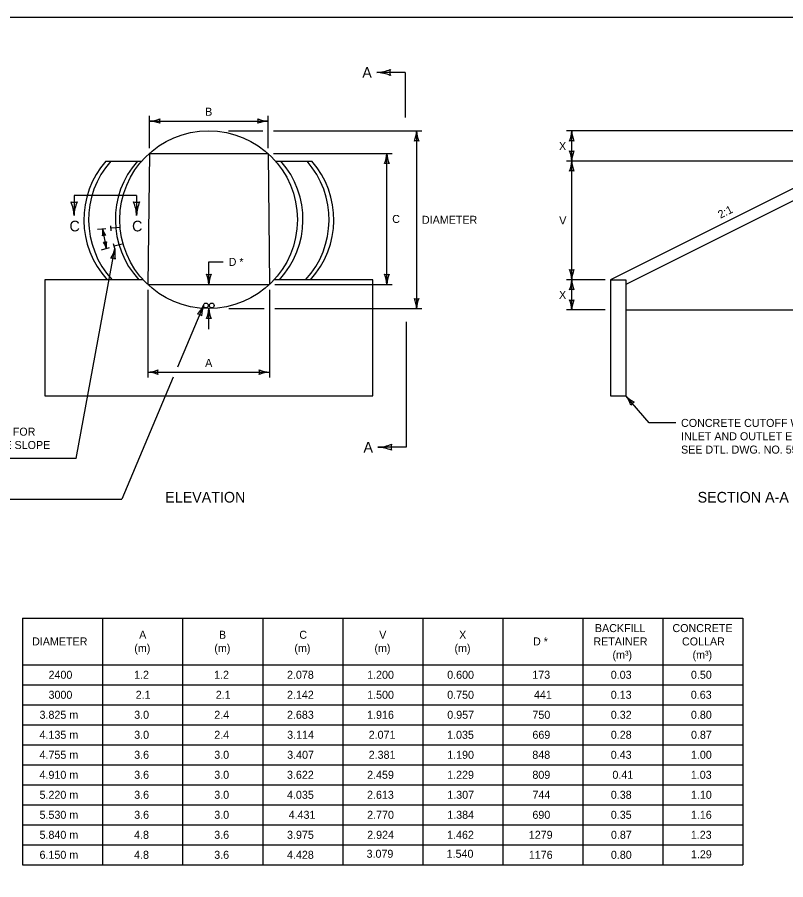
# Model space of a CAD drawing. Extents: x 49991.4 to 50021, y 49987.6 to 50011.4.
# Drawn here: x 50003.93 to 50009.69, y 49992.53 to 49999 of the extents above; entities that cross this region are included whole.
import ezdxf

# ---------------------------------------------------------------- set-up
doc = ezdxf.new("R2010")
doc.units = 0
for name, color, linetype in [('Level 1', 7, 'Continuous'), ('Level 2', 7, 'Continuous'), ('Level 3', 7, 'Continuous'), ('Level 4', 7, 'Continuous'), ('Level 6', 7, 'Continuous')]:
    doc.layers.add(name, color=color, linetype=linetype)

msp = doc.modelspace()

# ---------------------------------------------------------------- linework, layer by layer
at = {"layer": 'Level 1'}
for p, q in [((50004.5961, 49997.9206), (50004.8654, 49997.9206)), ((50005.8667, 49997.9206), (50006.1399, 49997.9206)), ((50010.1574, 49997.9206), (50008.3776, 49997.0307)), ((50010.3438, 49997.9206), (50008.4946, 49996.996)), ((50004.6363, 49997.3988), (50004.6331, 49997.4356)), ((50004.7061, 49997.4235), (50004.6347, 49997.4172)), ((50004.6643, 49997.2641), (50004.6543, 49997.2996)), ((50004.7284, 49997.3012), (50004.6593, 49997.2818)), ((50004.8754, 49997.0307), (50004.1392, 49997.0307)), ((50004.1392, 49997.0307), (50004.1392, 49996.1603)), ((50004.9097, 49996.996), (50005.8221, 49996.996)), ((50006.5966, 49997.0307), (50005.8565, 49997.0307)), ((50006.5966, 49996.1603), (50006.5966, 49997.0307)), ((50008.3776, 49997.0307), (50008.3776, 49996.1603)), ((50008.3776, 49997.0307), (50008.4946, 49997.0307)), ((50008.4946, 49997.0307), (50008.4946, 49996.9917)), ((50008.4946, 49996.9917), (50008.4946, 49996.1603)), ((50008.4946, 49996.8045), (50010.4571, 49996.8045)), ((50008.3776, 49996.3989), (50008.3776, 49996.3989)), ((50004.1392, 49996.1603), (50006.5966, 49996.1603)), ((50008.3776, 49996.1603), (50008.4946, 49996.1603))]:
    msp.add_line(p, q, dxfattribs=at)
msp.add_lwpolyline([(49999.3835, 49998.9992), (50016.7501, 49998.9992), (50016.7501, 49987.7988), (49999.3835, 49987.7988)], close=True, dxfattribs=at)
for centre, radius in [((50005.3659, 49997.4814), 0.6662), ((50005.3461, 49996.8376), 0.0179), ((50005.3897, 49996.8376), 0.0179)]:
    msp.add_circle(centre, radius, dxfattribs=at)
for centre, start, end in [((50005.0969, 49997.4814), 138.75266, 222.57653), ((50005.6391, 49997.4814), 317.42347, 41.24734)]:
    msp.add_arc(centre, 0.6662, start, end, dxfattribs=at)
at = {"layer": 'Level 2'}
for p, q in [((50003.9717, 49994.4938), (50009.3715, 49994.4938)), ((50003.9717, 49994.4938), (50003.9717, 49992.6438)), ((50004.5715, 49994.4938), (50004.5715, 49992.6438)), ((50005.1715, 49994.4938), (50005.1715, 49992.6438)), ((50005.7715, 49994.4938), (50005.7715, 49992.6438)), ((50006.3715, 49994.4938), (50006.3715, 49992.6438)), ((50006.9715, 49994.4938), (50006.9715, 49992.6438)), ((50007.5715, 49994.4938), (50007.5715, 49992.6438)), ((50008.1715, 49994.4938), (50008.1715, 49992.6438)), ((50008.7715, 49994.4938), (50008.7715, 49992.6438)), ((50009.3715, 49994.4938), (50009.3715, 49992.6438)), ((50003.9717, 49994.1438), (50009.3715, 49994.1438)), ((50003.9717, 49993.9938), (50009.3715, 49993.9938)), ((50003.9717, 49993.8438), (50009.3715, 49993.8438)), ((50003.9717, 49993.6938), (50009.3715, 49993.6938)), ((50003.9717, 49993.5438), (50009.3715, 49993.5438)), ((50003.9717, 49993.3938), (50009.3715, 49993.3938)), ((50003.9717, 49993.2438), (50009.3715, 49993.2438)), ((50003.9717, 49993.0938), (50009.3715, 49993.0938)), ((50003.9717, 49992.9438), (50009.3715, 49992.9438)), ((50003.9717, 49992.7938), (50009.3715, 49992.7938)), ((50003.9719, 49992.6438), (50009.3717, 49992.6438))]:
    msp.add_line(p, q, dxfattribs=at)
at = {"layer": 'Level 3'}
for p, q in [((50004.9237, 49998.0177), (50004.9237, 49998.2609)), ((50004.9237, 49998.2209), (50005.812, 49998.2209)), ((50005.812, 49998.0177), (50005.812, 49998.2609)), ((50005.5159, 49998.1464), (50005.772, 49998.1464)), ((50005.852, 49998.1464), (50006.9653, 49998.1464)), ((50006.9253, 49998.1464), (50006.9253, 49996.8141)), ((50010.1174, 49998.1464), (50008.0477, 49998.1464)), ((50008.0877, 49997.9204), (50008.0877, 49998.1464)), ((50005.852, 49997.9777), (50006.7424, 49997.9777)), ((50006.7024, 49996.996), (50006.7024, 49997.9777)), ((50010.1174, 49997.9206), (50008.0477, 49997.9206)), ((50008.0877, 49997.0307), (50008.0877, 49997.9206)), ((50004.5949, 49997.4135), (50004.5323, 49997.408)), ((50004.5721, 49997.4115), (50004.5992, 49997.2644)), ((50004.374, 49995.6917), (50004.6643, 49997.2641)), ((50004.6209, 49997.2705), (50004.5607, 49997.2536)), ((50005.3679, 49996.996), (50005.3679, 49997.165)), ((50005.3679, 49997.165), (50005.4765, 49997.165)), ((50005.8621, 49996.996), (50006.7424, 49996.996)), ((50008.3376, 49997.0307), (50008.0477, 49997.0307)), ((50008.0877, 49996.8045), (50008.0877, 49997.0307)), ((50004.9097, 49996.956), (50004.9097, 49996.2976)), ((50005.8221, 49996.956), (50005.8221, 49996.2976)), ((50005.3282, 49996.8376), (50005.1328, 49996.3745)), ((50005.3679, 49996.6601), (50005.3679, 49996.8153)), ((50005.5179, 49996.8141), (50005.7821, 49996.8141)), ((50005.8621, 49996.8141), (50006.9653, 49996.8141)), ((50008.3376, 49996.8045), (50008.0477, 49996.8045)), ((50004.9097, 49996.3376), (50005.8221, 49996.3376)), ((50005.1016, 49996.3007), (50004.7157, 49995.3864)), ((50008.6679, 49995.9573), (50008.4946, 49996.1603)), ((50008.8674, 49995.9573), (50008.6679, 49995.9573)), ((50004.374, 49995.6917), (50003.7773, 49995.6917)), ((50003.6357, 49995.3864), (50004.7157, 49995.3864))]:
    msp.add_line(p, q, dxfattribs=at)
for centre, radius, start, end in [((50006.6115, 49998.8956), 0.3107, 272.82731, 292.07716), ((50006.7978, 49998.5853), 0.073, 162.13882, 197.86118), ((50006.6146, 49998.2891), 0.2964, 67.45601, 87.63952), ((50004.9122, 49998.4536), 0.233, 272.82731, 292.07716), ((50004.9145, 49997.9988), 0.2223, 67.45601, 87.63952), ((50005.0519, 49998.2209), 0.0548, 162.13882, 197.86118), ((50005.8212, 49998.443), 0.2223, 247.45601, 267.63952), ((50005.6838, 49998.2209), 0.0548, 342.13882, 17.86118), ((50005.8235, 49997.9882), 0.233, 92.82731, 112.07716), ((50006.7032, 49998.1556), 0.2223, 337.45601, 357.63952), ((50007.158, 49998.1579), 0.233, 182.82731, 202.07716), ((50007.8656, 49998.1556), 0.2223, 337.45601, 357.63952), ((50008.3204, 49998.1579), 0.233, 182.82731, 202.07716), ((50006.9253, 49998.0182), 0.0548, 72.13882, 107.86118), ((50008.0877, 49998.0182), 0.0548, 72.13882, 107.86118), ((50006.4803, 49997.9869), 0.2223, 337.45601, 357.63952), ((50006.9351, 49997.9892), 0.233, 182.82731, 202.07716), ((50008.0877, 49998.0488), 0.0548, 252.13882, 287.86118), ((50007.855, 49997.9091), 0.233, 2.82731, 22.07716), ((50008.3098, 49997.9114), 0.2223, 157.45601, 177.63952), ((50006.7024, 49997.8495), 0.0548, 72.13882, 107.86118), ((50007.8656, 49997.9298), 0.2223, 337.45601, 357.63952), ((50008.3204, 49997.9321), 0.233, 182.82731, 202.07716), ((50008.0877, 49997.7924), 0.0548, 72.13882, 107.86118), ((50004.3574, 49997.6844), 0.073, 252.13882, 287.86118), ((50004.0471, 49997.4981), 0.3107, 2.82731, 22.07716), ((50004.6536, 49997.5012), 0.2964, 157.45601, 177.63952), ((50004.8264, 49997.6844), 0.073, 252.13882, 287.86118), ((50004.5161, 49997.4981), 0.3107, 2.82731, 22.07716), ((50005.1226, 49997.5012), 0.2964, 157.45601, 177.63952), ((50004.4182, 49997.3909), 0.1553, 348.39578, 7.64563), ((50004.7166, 49997.4444), 0.1482, 192.83342, 213.01693), ((50004.5877, 49997.3275), 0.0365, 82.61176, 118.33412), ((50004.5837, 49997.3484), 0.0365, 262.61176, 298.33412), ((50004.4547, 49997.2315), 0.1482, 12.83342, 33.01693), ((50004.7532, 49997.2851), 0.1553, 168.39578, 187.64563), ((50004.4475, 49997.3134), 0.2223, 326.99572, 347.17923), ((50004.8952, 49997.2332), 0.233, 172.36702, 191.61687), ((50004.641, 49997.138), 0.0548, 61.67853, 97.40089), ((50005.3679, 49997.1242), 0.0548, 252.13882, 287.86118), ((50005.1352, 49996.9845), 0.233, 2.82731, 22.07716), ((50005.59, 49996.9868), 0.2223, 157.45601, 177.63952), ((50006.7024, 49997.1242), 0.0548, 252.13882, 287.86118), ((50006.4697, 49996.9845), 0.233, 2.82731, 22.07716), ((50006.9245, 49996.9868), 0.2223, 157.45601, 177.63952), ((50008.0877, 49997.1589), 0.0548, 252.13882, 287.86118), ((50007.855, 49997.0192), 0.233, 2.82731, 22.07716), ((50008.3098, 49997.0215), 0.2223, 157.45601, 177.63952), ((50007.8656, 49997.0399), 0.2223, 337.45601, 357.63952), ((50008.3204, 49997.0422), 0.233, 182.82731, 202.07716), ((50008.0877, 49996.9025), 0.0548, 72.13882, 107.86118), ((50006.9253, 49996.9423), 0.0548, 252.13882, 287.86118), ((50006.6926, 49996.8026), 0.233, 2.82731, 22.07716), ((50007.1474, 49996.8049), 0.2223, 157.45601, 177.63952), ((50008.0877, 49996.9327), 0.0548, 252.13882, 287.86118), ((50007.855, 49996.793), 0.233, 2.82731, 22.07716), ((50008.3098, 49996.7953), 0.2223, 157.45601, 177.63952), ((50005.1271, 49996.9324), 0.2223, 314.57494, 334.75844), ((50005.5471, 49996.7577), 0.233, 159.94624, 179.19609), ((50005.1458, 49996.8244), 0.2223, 337.45601, 357.63952), ((50005.6006, 49996.8267), 0.233, 182.82731, 202.07716), ((50005.2784, 49996.7194), 0.0548, 49.25774, 84.9801), ((50005.3679, 49996.687), 0.0548, 72.13882, 107.86118), ((50004.8982, 49996.5703), 0.233, 272.82731, 292.07716), ((50004.9005, 49996.1155), 0.2223, 67.45601, 87.63952), ((50005.0379, 49996.3376), 0.0548, 162.13882, 197.86118), ((50005.8313, 49996.5597), 0.2223, 247.45601, 267.63952), ((50005.6939, 49996.3376), 0.0548, 342.13882, 17.86118), ((50005.8336, 49996.1049), 0.233, 92.82731, 112.07716), ((50008.3197, 49996.023), 0.2223, 17.94522, 38.12873), ((50008.6641, 49996.3201), 0.233, 223.31652, 242.56637), ((50008.5779, 49996.0628), 0.0548, 112.62803, 148.35039), ((50006.6203, 49996.085), 0.3107, 272.82731, 292.07716), ((50006.6234, 49995.4785), 0.2964, 67.45601, 87.63952), ((50006.8066, 49995.7747), 0.073, 162.13882, 197.86118)]:
    msp.add_arc(centre, radius, start, end, dxfattribs=at)
at = {"layer": 'Level 4'}
for p, q in [((50004.9237, 49997.9777), (50004.9097, 49996.996)), ((50004.9237, 49997.9777), (50005.812, 49997.9777)), ((50005.812, 49997.9777), (50005.8221, 49996.996))]:
    msp.add_line(p, q, dxfattribs=at)
for centre, start, end in [((50005.1331, 49997.4814), 138.75266, 222.57653), ((50005.3333, 49997.4814), 138.75266, 222.57653), ((50005.4073, 49997.4814), 317.42347, 41.24734), ((50005.6029, 49997.4814), 317.42347, 41.24734)]:
    msp.add_arc(centre, 0.6662, start, end, dxfattribs=at)
at = {"layer": 'Level 6'}
for p, q in [((50006.8394, 49998.5853), (50006.6268, 49998.5853)), ((50006.8394, 49998.5853), (50006.8394, 49998.2464)), ((50004.8264, 49997.6634), (50004.3574, 49997.6634)), ((50004.3574, 49997.6634), (50004.3574, 49997.5134)), ((50004.8264, 49997.6634), (50004.8264, 49997.5134)), ((50006.8482, 49996.7141), (50006.8482, 49995.7747)), ((50006.8482, 49995.7747), (50006.6356, 49995.7747))]:
    msp.add_line(p, q, dxfattribs=at)

# ---------------------------------------------------------------- texts
at = {"layer": 'Level 2'}
for s, height, p in [('A', 0.08, (50006.5181, 49998.5453)), ('B', 0.06, (50005.3401, 49998.2609)), ('X', 0.06, (50007.9927, 49998.0034)), ('C', 0.06, (50006.7424, 49997.4568)), ('DIAMETER', 0.06, (50006.9653, 49997.4502)), ('V', 0.06, (50007.9943, 49997.4456)), ('C', 0.08, (50004.3234, 49997.3934)), ('C', 0.08, (50004.7924, 49997.3934)), ('D *', 0.06, (50005.5165, 49997.135)), ('X', 0.06, (50007.9927, 49996.8876)), ('A', 0.06, (50005.3402, 49996.3776)), ('CONCRETE CUTOFF WALL', 0.06, (50008.9074, 49995.9273)), ('APPROX. 455 CENTERS FOR', 0.06, (50002.9577, 49995.8617)), ('INLET AND OUTLET END', 0.06, (50008.9074, 49995.8273)), ('LENGTH OF CONCRETE SLOPE', 0.06, (50002.9577, 49995.7617)), ('A', 0.08, (50006.5269, 49995.7347)), ('SEE DTL. DWG. NO. 552-00', 0.06, (50008.9074, 49995.7273)), ('ELEVATION', 0.08, (50005.0409, 49995.3602)), ('SECTION A-A', 0.08, (50009.0318, 49995.3602)), ('A', 0.06, (50004.8459, 49994.3388)), ('B', 0.06, (50005.4439, 49994.3388)), ('C', 0.06, (50006.0461, 49994.3388)), ('V', 0.06, (50006.6449, 49994.3388)), ('X', 0.06, (50007.2441, 49994.3388)), ('BACKFILL', 0.06, (50008.2618, 49994.3888)), ('CONCRETE', 0.06, (50008.843, 49994.3888)), ('DIAMETER', 0.06, (50004.0432, 49994.2888)), ('D *', 0.06, (50007.7978, 49994.2888)), ('RETAINER', 0.06, (50008.2502, 49994.2888)), ('COLLAR', 0.06, (50008.9143, 49994.2888)), ('(m)', 0.06, (50004.8092, 49994.2388)), ('(m)', 0.06, (50005.4092, 49994.2388)), ('(m)', 0.06, (50006.0092, 49994.2388)), ('(m)', 0.06, (50006.6092, 49994.2388)), ('(m)', 0.06, (50007.2092, 49994.2388)), ('(m³)', 0.06, (50008.3934, 49994.1888)), ('(m³)', 0.06, (50008.9934, 49994.1888)), ('2400', 0.06, (50004.1664, 49994.0388)), ('1.2', 0.06, (50004.8076, 49994.0388)), ('1.2', 0.06, (50005.4076, 49994.0388)), ('2.078', 0.06, (50005.9539, 49994.0388)), ('1.200', 0.06, (50006.5546, 49994.0388)), ('0.600', 0.06, (50007.1546, 49994.0388)), ('173', 0.06, (50007.7925, 49994.0388)), ('0.03', 0.06, (50008.3806, 49994.0388)), ('0.50', 0.06, (50008.9815, 49994.0388)), ('3000', 0.06, (50004.1664, 49993.8888)), ('2.1', 0.06, (50004.8198, 49993.8888)), ('2.1', 0.06, (50005.4198, 49993.8888)), ('2.142', 0.06, (50005.9538, 49993.8888)), ('1.500', 0.06, (50006.5546, 49993.8888)), ('0.750', 0.06, (50007.1546, 49993.8888)), ('441', 0.06, (50007.8047, 49993.8888)), ('0.13', 0.06, (50008.3806, 49993.8888)), ('0.63', 0.06, (50008.9806, 49993.8888)), ('3.825 m', 0.06, (50004.0989, 49993.7388)), ('3.0', 0.06, (50004.8084, 49993.7388)), ('2.4', 0.06, (50005.4088, 49993.7388)), ('2.683', 0.06, (50005.9537, 49993.7388)), ('1.916', 0.06, (50006.5544, 49993.7388)), ('0.957', 0.06, (50007.1551, 49993.7388)), ('750', 0.06, (50007.7933, 49993.7388)), ('0.32', 0.06, (50008.3807, 49993.7388)), ('0.80', 0.06, (50008.9815, 49993.7388)), ('4.135 m', 0.06, (50004.0989, 49993.5888)), ('3.0', 0.06, (50004.8084, 49993.5888)), ('2.4', 0.06, (50005.4088, 49993.5888)), ('3.114', 0.06, (50005.9549, 49993.5888)), ('2.071', 0.06, (50006.566, 49993.5888)), ('1.035', 0.06, (50007.154, 49993.5888)), ('669', 0.06, (50007.7932, 49993.5888)), ('0.28', 0.06, (50008.3809, 49993.5888)), ('0.87', 0.06, (50008.982, 49993.5888)), ('4.755 m', 0.06, (50004.0989, 49993.4388)), ('3.6', 0.06, (50004.8083, 49993.4388)), ('3.0', 0.06, (50005.4084, 49993.4388)), ('3.407', 0.06, (50005.9551, 49993.4388)), ('2.381', 0.06, (50006.566, 49993.4388)), ('1.190', 0.06, (50007.1546, 49993.4388)), ('848', 0.06, (50007.7927, 49993.4388)), ('0.43', 0.06, (50008.3806, 49993.4388)), ('1.00', 0.06, (50008.9815, 49993.4388)), ('4.910 m', 0.06, (50004.0989, 49993.2888)), ('3.6', 0.06, (50004.8083, 49993.2888)), ('3.0', 0.06, (50005.4084, 49993.2888)), ('3.622', 0.06, (50005.9538, 49993.2888)), ('2.459', 0.06, (50006.5544, 49993.2888)), ('1.229', 0.06, (50007.1544, 49993.2888)), ('809', 0.06, (50007.7932, 49993.2888)), ('0.41', 0.06, (50008.3929, 49993.2888)), ('1.03', 0.06, (50008.9806, 49993.2888)), ('5.220 m', 0.06, (50004.0989, 49993.1388)), ('3.6', 0.06, (50004.8083, 49993.1388)), ('3.0', 0.06, (50005.4084, 49993.1388)), ('4.035', 0.06, (50005.954, 49993.1388)), ('2.613', 0.06, (50006.5537, 49993.1388)), ('1.307', 0.06, (50007.1551, 49993.1388)), ('744', 0.06, (50007.7937, 49993.1388)), ('0.38', 0.06, (50008.3809, 49993.1388)), ('1.10', 0.06, (50008.9815, 49993.1388)), ('5.530 m', 0.06, (50004.0989, 49992.9888)), ('3.6', 0.06, (50004.8083, 49992.9888)), ('3.0', 0.06, (50005.4084, 49992.9888)), ('4.431', 0.06, (50005.966, 49992.9888)), ('2.770', 0.06, (50006.5546, 49992.9888)), ('1.384', 0.06, (50007.1549, 49992.9888)), ('690', 0.06, (50007.7933, 49992.9888)), ('0.35', 0.06, (50008.3809, 49992.9888)), ('1.16', 0.06, (50008.9814, 49992.9888)), ('5.840 m', 0.06, (50004.0989, 49992.8388)), ('4.8', 0.06, (50004.8078, 49992.8388)), ('3.6', 0.06, (50005.4083, 49992.8388)), ('3.975', 0.06, (50005.954, 49992.8388)), ('2.924', 0.06, (50006.5549, 49992.8388)), ('1.462', 0.06, (50007.1538, 49992.8388)), ('1279', 0.06, (50007.7662, 49992.8388)), ('0.87', 0.06, (50008.382, 49992.8388)), ('1.23', 0.06, (50008.9806, 49992.8388)), ('6.150 m', 0.06, (50004.0989, 49992.6888)), ('4.8', 0.06, (50004.8078, 49992.6888)), ('3.6', 0.06, (50005.4083, 49992.6888)), ('4.428', 0.06, (50005.9539, 49992.6888)), ('3.079', 0.06, (50006.5502, 49992.6966)), ('1.540', 0.06, (50007.1504, 49992.6966)), ('1176', 0.06, (50007.7663, 49992.6888)), ('0.80', 0.06, (50008.3815, 49992.6888)), ('1.29', 0.06, (50008.9814, 49992.6925))]:
    msp.add_text(s, height=height, dxfattribs=at).set_placement(p)
msp.add_text('2:1', height=0.06, rotation=26.56505, dxfattribs=at).set_placement((50009.2023, 49997.4878))

doc.saveas('drawing.dxf')
